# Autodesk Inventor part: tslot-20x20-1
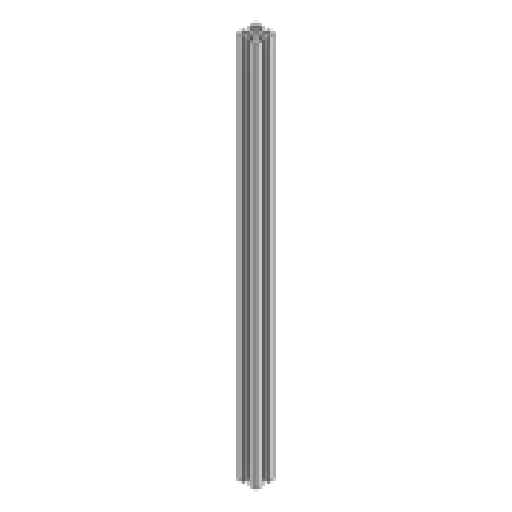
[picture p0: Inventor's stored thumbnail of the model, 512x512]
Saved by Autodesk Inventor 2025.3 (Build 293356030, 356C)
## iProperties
Created: 2025-03
Part Number: tslot-20x20-1
Material: Generico
Document SubType Name: Modeling
Designer: Ryzen5700u
Density: 1 g/cm^3
Appearance: Default
Author: Ryzen5700u
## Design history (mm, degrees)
feature "Base1"
sketch "Schizzo1"
  geometry: L1 (3.761, -16)-(4.7, -16) reference; L2 (3.761, -16)-(0.7, -12.939) reference; L3 (0.7, -12.939)-(0.7, -10.52) reference; L4 (0.4, -10)-(0.7, -10.52) reference; L5 (0.4, -10)-(0.7, -9.48) reference; L6 (0.7, -7.061)-(0.7, -9.48) reference; L7 (3.761, -4)-(0.7, -7.061) reference; L8 (3.761, -4)-(4.7, -4) reference; L9 (4.7, -4)-(4.7, -7) reference; L10 (4.7, -7)-(6.4, -7) reference; L11 (6.7, -6.7)-(6.7, -1) reference; L12 (5.7, 0)-(0, 0) reference; L13 (-0.3, -2)-(-0.3, -0.3) reference; L14 (2.7, -2)-(-0.3, -2) reference; L15 (2.7, -2.939)-(2.7, -2) reference; L16 (2.7, -2.939)-(-0.361, -6) reference; L17 (-0.361, -6)-(-2.78, -6) reference; L18 (-3.3, -6.3)-(-2.78, -6) reference; L19 (-3.3, -6.3)-(-3.82, -6) reference; L20 (-6.239, -6)-(-3.82, -6) reference; L21 (-9.3, -2.939)-(-6.239, -6) reference; L22 (-9.3, -2.939)-(-9.3, -2) reference; L23 (-9.3, -2)-(-6.3, -2) reference; L24 (-6.3, -2)-(-6.3, -0.3) reference; L25 (-12.3, 0)-(-6.6, 0) reference; L26 (-13.3, -6.7)-(-13.3, -1) reference; L27 (-11.3, -7)-(-13, -7) reference; L28 (-11.3, -4)-(-11.3, -7) reference; L29 (-10.361, -4)-(-11.3, -4) reference; L30 (-10.361, -4)-(-7.3, -7.061) reference; L31 (-7.3, -7.061)-(-7.3, -9.48) reference; L32 (-7, -10)-(-7.3, -9.48) reference; L33 (-7, -10)-(-7.3, -10.52) reference; L34 (-7.3, -12.939)-(-7.3, -10.52) reference; L35 (-10.361, -16)-(-7.3, -12.939) reference; L36 (-10.361, -16)-(-11.3, -16) reference; L37 (-11.3, -16)-(-11.3, -13) reference; L38 (-11.3, -13)-(-13, -13) reference; L39 (-13.3, -13.3)-(-13.3, -19) reference; L40 (-12.3, -20)-(-6.6, -20) reference; L41 (-6.3, -18)-(-6.3, -19.7) reference; L42 (-9.3, -18)-(-6.3, -18) reference; L43 (-9.3, -17.061)-(-9.3, -18) reference; L44 (-9.3, -17.061)-(-6.239, -14) reference; L45 (-6.239, -14)-(-3.82, -14) reference; L46 (-3.3, -13.7)-(-3.82, -14) reference; L47 (-3.3, -13.7)-(-2.78, -14) reference; L48 (-0.361, -14)-(-2.78, -14) reference; L49 (2.7, -17.061)-(-0.361, -14) reference; L50 (2.7, -17.061)-(2.7, -18) reference; L51 (2.7, -18)-(-0.3, -18) reference; L52 (-0.3, -18)-(-0.3, -19.7) reference; L53 (5.7, -20)-(0, -20) reference; L54 (6.7, -13.3)-(6.7, -19) reference; L55 (4.7, -13)-(6.4, -13) reference; L56 (4.7, -16)-(4.7, -13) reference; C1 r 2.1 at (-3.3, -10) reference; A1 r 0.3 centre (6.4, -6.7) between (6.4, -7) and (6.7, -6.7) reference; A2 r 1 centre (5.7, -1) between (6.7, -1) and (5.7, 0) reference; A3 r 0.3 centre (0, -0.3) between (0, 0) and (-0.3, -0.3) reference; A4 r 0.3 centre (-6.6, -0.3) between (-6.3, -0.3) and (-6.6, 0) reference; A5 r 1 centre (-12.3, -1) between (-12.3, 0) and (-13.3, -1) reference; A6 r 0.3 centre (-13, -6.7) between (-13.3, -6.7) and (-13, -7) reference; A7 r 0.3 centre (-13, -13.3) between (-13, -13) and (-13.3, -13.3) reference; A8 r 1 centre (-12.3, -19) between (-13.3, -19) and (-12.3, -20) reference; A9 r 0.3 centre (-6.6, -19.7) between (-6.6, -20) and (-6.3, -19.7) reference; A10 r 0.3 centre (0, -19.7) between (-0.3, -19.7) and (0, -20) reference; A11 r 1 centre (5.7, -19) between (5.7, -20) and (6.7, -19) reference; A12 r 0.3 centre (6.4, -13.3) between (6.7, -13.3) and (6.4, -13) reference; 1 further point
extrude "Estrusione1" join sketch "Schizzo1" distance "d0" = 390; taper "d1" = 0 deg
node "Solido1"
node "Linea chiusa proiettata1"
